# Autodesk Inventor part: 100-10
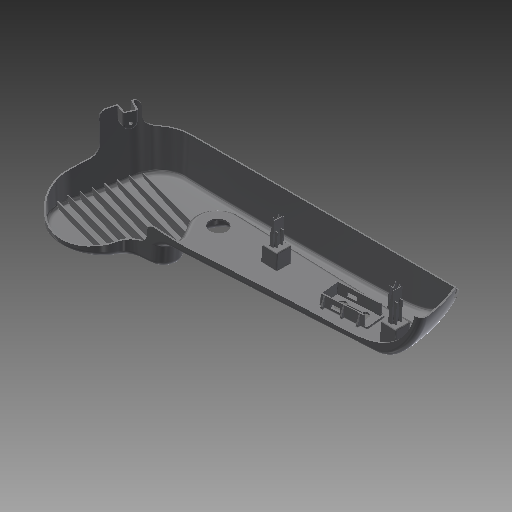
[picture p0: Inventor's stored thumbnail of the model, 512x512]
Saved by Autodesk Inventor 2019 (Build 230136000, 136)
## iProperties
Company: Autodesk Inc.
Created: 2007-12
Part Number: 100-10
Document SubType Name: Modeling
Designer: Autodesk Inc.
Density: 1.06 g/cm^3
Material: ABS Plastic
Description: SIDE PLASTIC COVER
Appearance: Smooth - Medium Gray
Component Category: Side Component
Author: Inventor
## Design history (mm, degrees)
feature "Surface1"
feature "Surface2"
feature "Surface3"
feature "Surface4"
feature "OffsetSrf1" dims "d0" = 2, "d1" = 2
feature "OffsetSrf2" dims "d2" = 5
feature "Extend1" dims "d3" = 20
feature "Extend2" dims "d4" = 100
feature "Stitch Surface1" dims "d174" = 0.254 (derived)
workplane "Work Plane1"
sketch "Sketch1"
  geometry: L1 (31.666, 125)-(-201.012, 125); 1 further point
  constraints: 2 end point, 1 horizontal
  dimensions: "d10" = 125 distance from line of point (0, 0) L1
extrude_surface "ExtrusionSrf1" sketch "Sketch1" dims "d11" = 266.7, "d12" = 0
feature "Surface5"
feature "Stitch Surface2" dims "d175" = 0.254 (derived)
fillet "Fillet1" dims "d13" = 20
split "Split1"
split "Split2"
split "Split3"
delete_face "Delete Face1"
sketch "Sketch3"
  geometry: L1 (0, 70)-(-50, 70); L2 (-65, 55)-(-65, 0); A1 r 15 centre (-50, 55) between (-50, 70) and (-65, 55); 1 further point
  constraints: 4 end point, 2 point on circle, 2 tangent, 1 centre point, 1 horizontal, 1 horizontal alignment, 1 perpendicular, 1 vertical alignment
  dimensions: "d14" = 70 distance from line of point (0, 0) L1; "d15" = 65 distance from line of point (0, 0) L2; "d16" = 15 radius of A1
extrude_surface "ExtrusionSrf2" sketch "Sketch3" dims "d17" = 673.1, "d18" = 0
workplane "Work Plane2"
split "Split4"
split "Split5"
delete_face "Delete Face2"
sketch "Sketch4"
  geometry: A1 r 350 centre (41.225, 356.621) between (-33.955, 14.791) and (30.735, 6.778); 3 further points
  constraints: 2 point on circle, 1 centre point, 5 other
  dimensions: "d20" = 8 vertical distance of point (-34.055, 22.791) A1.start; "d21" = 350 radius of A1
split "Split6" sketch "Sketch4"
delete_face "Delete Face3"
thicken "Thicken1" dims "d22" = 2.5
fillet "Fillet2" dims "d23" = 10
fillet "Fillet3" dims "d24" = 10
sketch "Sketch5"
  geometry: C1 r 5.025 at (116.996, 110) reference; C2 r 15 at (116.996, 110)
  constraints: 1 centre point, 1 coincident
  dimensions: "d25" = 30 diameter of C2
extrude "Extrusion1" cut sketch "Sketch5" extent not by distance; stored distance "d26" = 10; taper "d27" = 0 deg
sketch "Sketch6"
  geometry: L1 (16.863, -65.429)-(261.287, -65.429); L2 (0, 0)-(319.709, 0) reference; 1 further point; 1 other entity
  constraints: 2 end point, 1 parallel, 1 other
  dimensions: "d28" = 27 distance from line of L1 point (246.863, -38.429); "d29" = 230 horizontal distance of L1.start point (246.863, -38.429)
feature "iFeature3:1"
workpoint "Work Point1"
workpoint "Work Point2"
workpoint "Work Point3"
feature "iFeature8:2"
fillet "Fillet4" dims "d30" = 1
fillet "Fillet5" dims "d31" = 2
workpoint "Work Point4"
workpoint "Work Point5"
workpoint "Work Point6"
feature "iFeature8:3"
fillet "Fillet6" dims "d32" = 1
fillet "Fillet7" dims "d33" = 2
fillet "Fillet8" dims "d34" = 1
feature "Surface7"
workplane "Work Plane3"
workaxis "Work Axis1"
patch "Boundary Patch2" dims "d47" = 0, "d48" = 0
feature "Surface8"
sketch "Sketch12"
  geometry: L1 (24.5, 21)-(5.5, 21) reference; L2 (5.5, 27)-(24.5, 27) reference; L3 (24.5, 21)-(5.5, 27); L4 (-361.35, 41.429)-(256.934, 41.429) reference; L5 (25, 24)-(25, 41.429); L6 (5, 24)-(5, 41.429); C1 r 2.75 at (15, 24); A1 r 10 centre (15, 24) between (25, 24) and (5, 24); 1 further point
  constraints: 6 end point, 2 centre point, 2 coincident, 2 point on circle, 2 point on line, 2 tangent, 1 midpoint, 1 parallel, 1 perpendicular
  dimensions: "d83" = 20 diameter of A1; "d84" = 5.5 diameter of C1
extrude "Extrusion4" join sketch "Sketch12" distance "d85" = 2.5; taper "d86" = 0 deg
extrude "Extrusion5" join sketch "Sketch12" stored distance "d87" = 50; taper "d88" = 0 deg
workplane "Work Plane4"
sketch "Sketch14"
  geometry: L1 (5, 24)-(5, 41.429) reference; L2 (25, 41.429)-(25, 24) reference; L3 (89.525, -67.484)-(90.11, -65.841) reference; L4 (5, 41.429)-(25, 41.429) reference; L5 (7.5, 24)-(7.5, 38.929); L6 (7.5, 38.929)-(22.5, 38.929); L7 (22.5, 38.929)-(22.5, 24); L8 (22.5, 38.929)-(22.5, 53.929); L9 (22.5, 53.929)-(7.5, 53.929); L10 (7.5, 53.929)-(7.5, 38.929); A1 r 10 centre (15, 24) between (5, 24) and (25, 24) reference; A2 r 7.5 centre (15, 24) between (7.5, 24) and (22.5, 24); 12 further points
  constraints: 12 end point, 2 collinear, 2 point on circle, 1 centre point, 1 perpendicular, 1 point on line, 16 other
  dimensions: "d98" = 2.5 distance between parallel lines of L2 L7; "d99" = 15 distance between parallel lines of L6 L9
extrude "Extrusion8" cut sketch "Sketch14" extent not by distance; stored distance "d100" = 50; taper "d101" = 3 deg
workplane "Work Plane6"
split "Split8"
feature "FaceDraft1" dims angle "d102" = 3 deg
sketch "Sketch16"
  geometry: L1 (-25, 24)-(-25, 41.429) reference; L2 (-5, 41.429)-(-5, 24) reference; L3 (-25, 41.429)-(-5, 41.429) reference; C1 r 2.75 at (-15, 24); A1 r 10 centre (-15, 24) between (-25, 24) and (-5, 24) reference
  constraints: 1 centre point, 1 coincident
  dimensions: "d103" = 5.5 diameter of C1
extrude "Extrusion9" cut sketch "Sketch16" extent not by distance; stored distance "d104" = 50; taper "d105" = 0 deg
fillet "Fillet23" dims "d107" = 1.5
fillet "Fillet24" dims "d108" = 3
fillet "Fillet25" dims "d109" = 1
fillet "Fillet26" dims "d110" = 2
workplane "Work Plane7"
sketch "Sketch17" dims "d118" = 10
  geometry: L1 (229.175, 211.817)-(293.224, 194.655); L2 (229.175, 211.817)-(215.205, 159.682); L3 (0, 27.871)-(0, 242.475) reference; L4 (224.775, 195.396)-(288.824, 178.234); L5 (220.375, 178.976)-(284.424, 161.814); L6 (215.975, 162.555)-(280.025, 145.393); L7 (211.575, 146.134)-(275.625, 128.972); L8 (207.175, 129.713)-(271.225, 112.551); L9 (202.775, 113.293)-(266.825, 96.131); L10 (198.375, 96.872)-(262.425, 79.71)
  constraints: 18 end point, 1 perpendicular, 22 other
  dimensions: "d112" = 75 deg angle of L1 L3; "d115" = 17 distance of L1.start L4.start
feature "Rib3" sketch "Sketch17" dims "d120" = 1.5, "d121" = 1, "d122" = 0.5 deg
fillet "Fillet27" dims "d123" = 0.5
workplane "Work Plane8"
workplane "Work Plane9"
sketch "Sketch18"
  geometry: L1 (539.384, 57.752)-(-304.194, 148.909) reference; L2 (68.703, 108.614)-(81.627, 107.217); L3 (72.33, 114.257)-(71.041, 102.326); L4 (79.289, 113.505)-(78, 101.574); 1 further point; 1 other entity
  constraints: 6 end point, 2 point on line, 1 parallel, 1 perpendicular, 1 other
  dimensions: "d125" = 3 distance from line of L4 L2.end; "d126" = 3 distance from line of L2.start L3; "d127" = 13 distance of L2.start L2.end; "d128" = 6 distance from line of L1 L4.start; "d129" = 6 distance from line of L1 L4.end; "d130" = 6 distance from line of L1 L3.start; "d131" = 6 distance from line of L1 L3.end; "d132" = 50 distance from line of point (16.758, 65.39) L3
feature "Rib4" sketch "Sketch18" dims "d133" = 1, "d134" = 1, "d135" = 1 deg
patch "Boundary Patch3" dims "d136" = 0, "d137" = 0
sketch "Sketch19"
  geometry: L1 (2.537, -0.923)-(7.753, 13.408); L2 (7.753, 13.408)-(-9.509, 18.232); L3 (-9.509, 18.232)-(-2.537, -0.923); L4 (0, 0)-(0, 20.344); C1 r 2.5 at (0, 0) reference; A1 r 2.7 centre (0, 0) between (2.537, -0.923) and (-2.537, -0.923); 1 further point
  constraints: 8 end point, 2 point on circle, 2 tangent, 1 centre point, 1 coincident, 1 vertical
  dimensions: "d138" = 0.2 radial gap between concentric circles of A1 C1; "d139" = 20 deg angle of L4 L1; "d140" = 20 deg angle of L4 L3; "d141" = 15 distance from line of point (0, 0) L2
extrude "Extrusion10" cut sketch "Sketch19" distance "d142" = 25.4; taper "d143" = 0 deg
fillet "Fillet28" dims "d144" = 1
fillet "Fillet29" dims "d145" = 1
fillet "Fillet30" dims "d146" = 1
fillet "Fillet31" dims "d147" = 1
fillet "Fillet32" dims "d148" = 0.5
fillet "Fillet33" dims "d149" = 0.5
sketch "Sketch20"
  geometry: L1 (539.384, 57.752)-(-304.194, 148.909) reference; L2 (280.47, 85.73)-(267.545, 87.127); L3 (269.883, 80.839)-(271.172, 92.77); L4 (276.842, 80.087)-(278.132, 92.018); 1 further point; 1 other entity
  constraints: 6 end point, 2 point on line, 1 parallel, 1 perpendicular, 1 other
  dimensions: "d151" = 13 distance of L2.end L2.start; "d152" = 3 distance from line of L2.start L4; "d153" = 3 distance from line of L2.end L3; "d154" = 6 distance from line of L1 L4.end; "d155" = 6 distance from line of L1 L4.start; "d156" = 6 distance from line of L1 L3.end; "d157" = 6 distance from line of L1 L3.start; "d158" = 250 distance from line of point (16.758, 65.39) L3
feature "Rib5" sketch "Sketch20" dims "d159" = 1, "d160" = 1, "d161" = 1 deg
sketch "Sketch21"
  geometry: L1 (0, 0)-(0, 13.676); L2 (2.537, -0.923)-(8.333, 15); L3 (8.333, 15)-(-8.333, 15); L4 (-8.333, 15)-(-2.537, -0.923); C1 r 2.5 at (0, 0) reference; A1 r 2.7 centre (0, 0) between (2.537, -0.923) and (-2.537, -0.923)
  constraints: 8 end point, 2 point on circle, 2 tangent, 1 centre point, 1 coincident, 1 perpendicular, 1 vertical
  dimensions: "d162" = 20 deg angle of L1 L4; "d163" = 20 deg angle of L1 L2; "d164" = 0.2 radial gap between concentric circles of A1 C1; "d165" = 15 distance from line of L3 C1.centre
extrude "Extrusion11" cut sketch "Sketch21" distance "d166" = 222.25; taper "d167" = 0 deg
fillet "Fillet34" dims "d168" = 1
fillet "Fillet35" dims "d169" = 1
fillet "Fillet36" dims "d170" = 1
fillet "Fillet37" dims "d171" = 1
fillet "Fillet38" dims "d172" = 0.5
fillet "Fillet39" dims "d173" = 0.5
body "Solid1"
body "Srf5"
body "Srf6"
node "Edges1"
node "Edges2"
body "Srf7"
body "Srf8"
body "Srf9"
sketch "Sketch2"
  geometry: L1 (236.74, 122.454)-(244.581, 340.953); L2 (244.581, 340.953)-(128.628, 329.837); L3 (128.628, 329.837)-(155.756, 97.766)
  constraints: 6 end point, 1 other
body "Srf12"
body "Srf13"
body "Srf14"
node "Reference1"
body "Srf16"
node "Projected Loop1"
body "Srf18"
body "Srf1"
body "Srf2"
body "Srf3"
body "Srf4"
feature "LoftSrf1" dims "d5" = 20, "d6" = 90 deg, "d7" = 20, "d8" = 90 deg
body "Srf10"
feature "Surface6"
body "Srf11"
patch "Boundary Patch1"
body "Srf15"
body "Srf17"
node "Project Cut Edges1"
other parameters: "d19" = -25, "d89" = 2.5, "d124" = 21, "d150" = 28
